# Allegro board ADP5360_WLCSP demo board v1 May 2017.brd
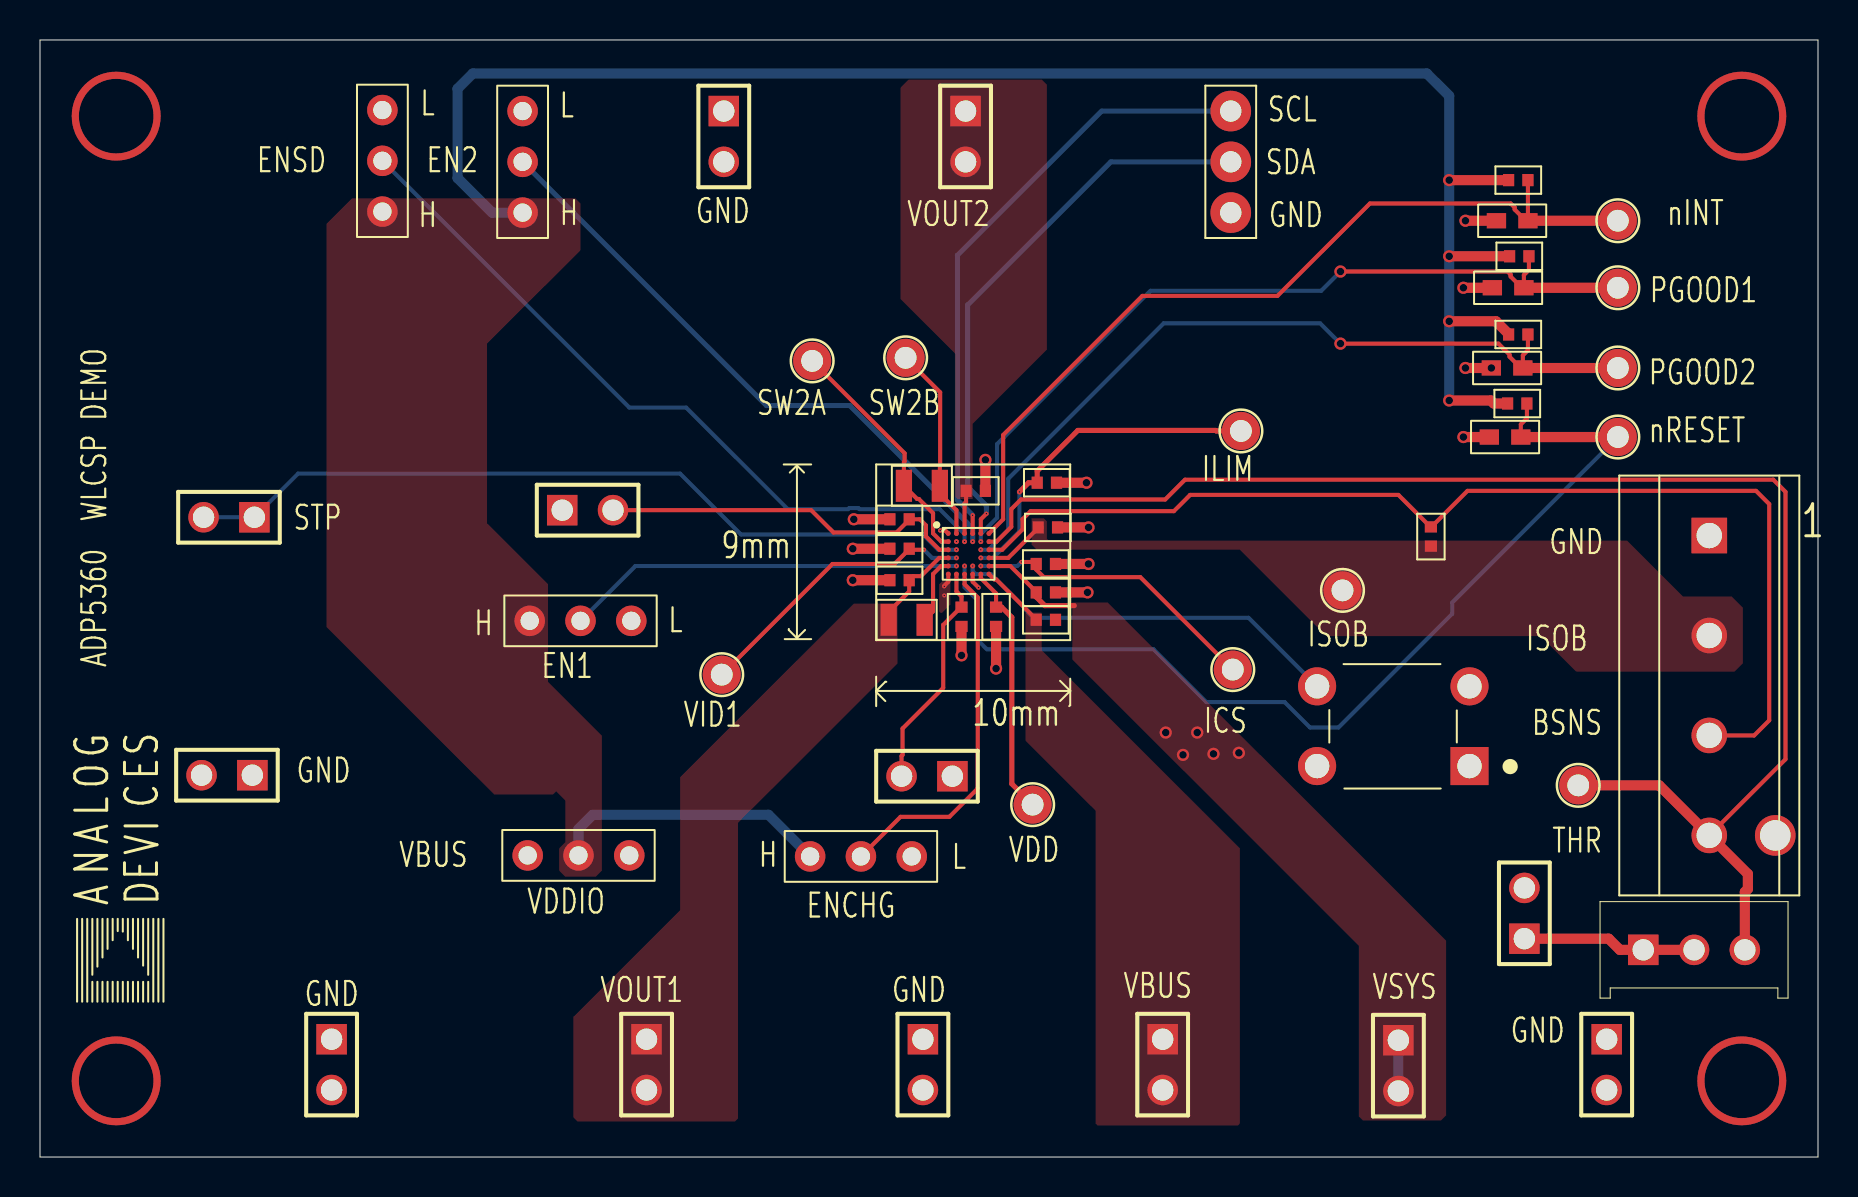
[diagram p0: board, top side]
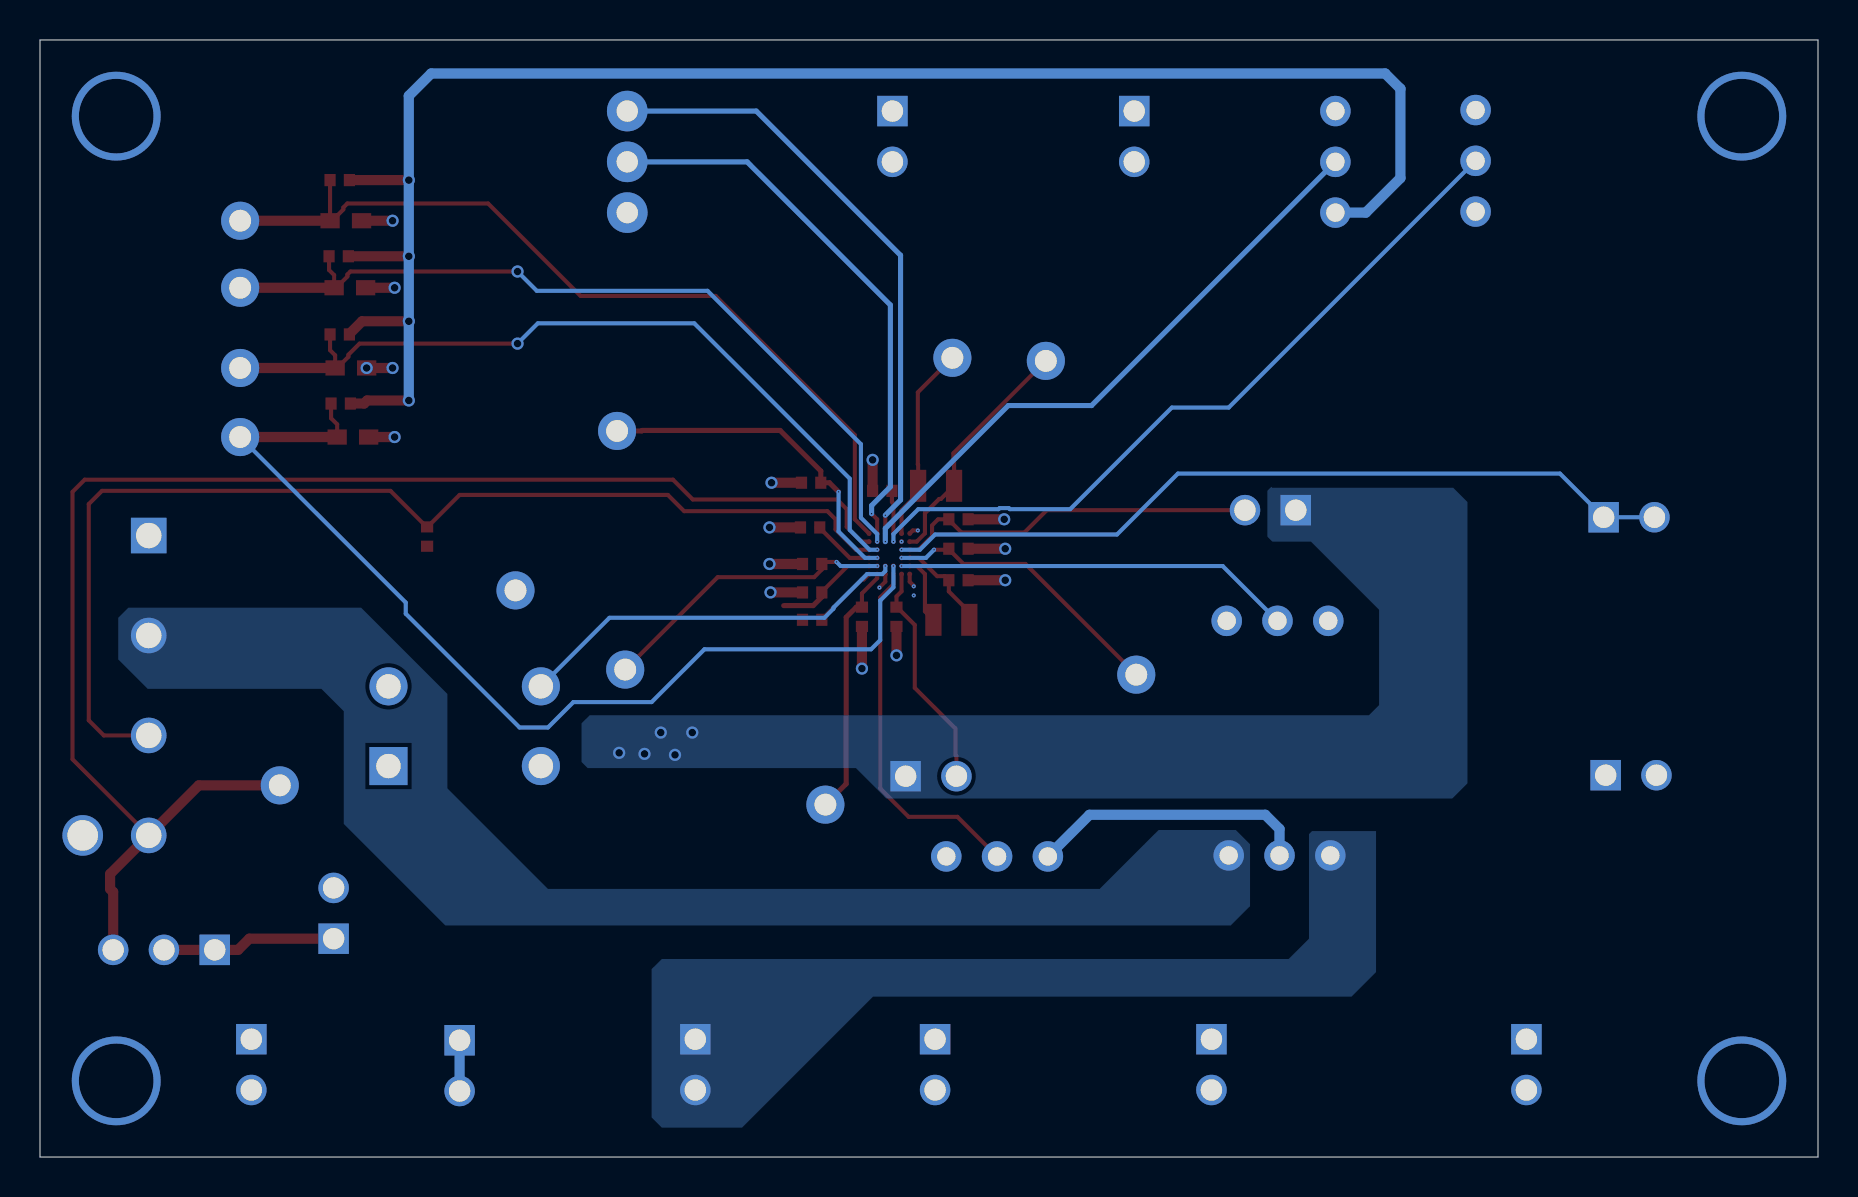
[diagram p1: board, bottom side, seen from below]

Outline 88.9 x 55.88 mm; copper layers: TOP, LAYER2, LAYER3, BOTTOM. Coordinates in mm from the lower left corner of the outline.

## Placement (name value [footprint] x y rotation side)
C1  2.2uF  [R0402]  50.29 26.87 0 top
C2  1uF  [R0402]  46.08 27.03 270 top
C3  1uF  [R0402]  47.8 27.03 270 top
C4  10uF  [R0402]  42.98 28.85 180 top
C5  1uF  [R0402]  50.29 28.24 0 top
C6  4.7uF  [R0402]  50.39 31.5 0 top
C7  1uF  [R0402]  42.98 31.9 180 top
C8  10uF  [R0402]  46.79 33.32 0 top
D1  LED  [CC0603]  73.61 46.84 180 top
D2  LED  [CC0603]  73.41 43.48 180 top
D3  LED  [CC0603]  73.36 39.47 180 top
D4  LED  [CC0603]  73.25 36.02 180 top
J1  VBUS  [HDR1X2]  56.13 5.89 90 top
J2  VSYS  [HDR1X2]  67.92 5.84 90 top
J3  VOUT1  [HDR1X2]  30.33 5.89 90 top
J4  4 HEADER  [CNTERM_4P-TYCO]  83.46 31.09 270 top
J5  STP  [HDR1X2]  10.72 32 0 top
J6  THR  [TESTPOINT75]  76.91 18.59 0 top
J7  VOUT2  [HDR1X2]  46.28 52.32 90 top
J8  I2C Connector  [JUMPER-3PIN]  59.54 47.24 0 top
J9  GND  [HDR1X2]  44.15 5.89 90 top
J10  GND  [HDR1X2]  78.33 5.89 90 top
J11  GND  [HDR1X2]  10.62 19.1 0 top
J12  GND  [HDR1X2]  14.58 5.89 90 top
J13  GND  [HDR1X2]  34.19 52.32 90 top
J18  1 Way Link  [HDR1X2]  74.22 10.92 270 top
JP1  2 Way Link  [JUMPER3]  24.49 26.82 0 top
JP2  2 Way Link  [JUMPER3]  38.51 15.04 0 top
JP3  2 Way Link  [JUMPER3]  24.13 47.24 90 top
JP4  2 Way Link  [JUMPER3]  17.12 47.29 90 top
JP5  2 Way Link  [JUMPER3]  24.38 15.09 0 top
L1  4.7uH  [INDUCTOR0806]  43.33 26.87 180 top
L2  4.7uH  [INDUCTOR0806]  44.09 33.58 0 top
NOREF  -  []  17.78 54.61 270 top
NOREF#2  -  []  -137.24 124.18 0 top
NOREF#3  -  []  0 0 90 top
NOREF#4  -  []  0 0 90 top
NOREF#5  -  []  0 50.8 0 top
R1  0R  [R0402]  69.55 31.04 270 top
R2  R_1  [R0402]  42.98 30.43 180 top
R3  R_1  [R0402]  50.34 33.73 180 top
R4  R_1  [R0402]  50.29 29.67 180 top
R5  5.1K  [R0402]  73.91 48.87 0 top
R6  5.1K  [R0402]  73.96 45.06 0 top
R7  5.1K  [R0402]  73.91 41.15 0 top
R8  5.1K  [R0402]  73.86 37.69 0 top
R9  THR  [SW_SPDT_MINI]  80.16 10.36 270 top
S1  Short  [HDR1X2]  45.62 19.05 0 top
S2  Short  [HDR1X2]  26.11 32.36 180 top
SW1  MR  [SWKT11]  71.48 19.56 180 top
T1  VDD  [TESTPOINT75]  49.63 17.63 0 top
T2  VID1  [TESTPOINT75]  34.09 24.13 0 top
T3  ISOB  [TESTPOINT75]  65.13 28.35 0 top
T4  ILIM  [TESTPOINT75]  60.05 36.32 0 top
T5  SW2A  [TESTPOINT75]  38.61 39.83 0 top
T6  ICS  [TESTPOINT75]  59.64 24.38 0 top
T7  SW2B  [TESTPOINT75]  43.28 39.98 0 top
T8  PGOOD1  [TESTPOINT75]  78.89 43.48 0 top
T9  nINT  [TESTPOINT75]  78.89 46.84 0 top
T10  RESET  [TESTPOINT75]  78.89 36.02 0 top
T11  PGOOD2  [TESTPOINT75]  78.89 39.47 0 top
U1  ADP5360  [ADP5360_WLCSP]  46.43 30.18 0 top

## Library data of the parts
C1-C8 = CAP/SM: Tolerance: TOL; User Part Number: UPN
D1-D4 = LED
J1-J3 J5 J7 J9-J13 = CON2
J4 = 4 HEADER: User Part Number: UPN; Tolerance: TOL
J6 T1-T11 = CON1_0
J8 = HEADER 3_0
J18 = 1_way_link
JP1-JP5 = 2_way_link: User Part Number: ***
L1 L2 = INDUCTOR/SM
R1-R8 = R_1: Tolerance: TOL; User Part Number: UPN
R9 = RESISTOR VAR
S1 S2 = Short Pad
SW1 = SW PUSHBUTTON_2: User Part Number: E004573; Tolerance: TOL
U1 = ADP5360_WLCSP

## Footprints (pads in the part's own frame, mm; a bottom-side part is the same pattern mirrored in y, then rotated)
ADP5360_WLCSP
  round 0.249 smd: A1(-1.021,1.021) A2(-0.61,1.016) A3(-0.203,1.016) A4(0.203,1.016) A5(0.61,1.016) A6(1.016,1.016) B1(-1.016,0.61) B2(-0.61,0.61) B3(-0.203,0.61) B4(0.203,0.61) B5(0.61,0.61) B6(1.016,0.61) C1(-1.016,0.203) C2(-0.61,0.203) C5(0.61,0.203) C6(1.016,0.203) D1(-1.016,-0.203) D2(-0.61,-0.203) D5(0.61,-0.203) D6(1.016,-0.203) E1(-1.016,-0.61) E2(-0.61,-0.61) E3(-0.203,-0.61) E4(0.203,-0.61) E5(0.61,-0.61) E6(1.016,-0.61) F1(-1.016,-1.016) F2(-0.61,-1.016) F3(-0.203,-1.016) F4(0.203,-1.016) F5(0.61,-1.016) F6(1.016,-1.016)
CC0603
  rect 0.965x0.762 smd: 1(-0.787,0) 2(0.787,0)
CNTERM_4P-TYCO
  round 2.032 hole 1.524: (15.001,3.299)
  rect 1.778x1.778 hole 1.27: 1(0,0)
  round 1.778 hole 1.27: 2(5.001,0) 3(10,0) 4(15.001,0)
HDR1X2
  rect 1.524x1.524 hole 1.067: 1(0,0)
  round 1.524 hole 1.067: 2(-2.54,0)
INDUCTOR0806
  rect 0.813x1.6 smd: 1(-0.899,0) 2(0.899,0)
JUMPER3
  round 1.524 hole 0.914: 1(0,0) 2(2.54,0) 3(5.08,0)
JUMPER-3PIN
  round 2.032 hole 1.067: 1(0,0) 2(0,2.54) 3(0,5.08)
R0402
  rect 0.559x0.61 smd: 1(-0.483,0) 2(0.483,0)
SW_SPDT_MINI
  rect 1.524x1.524 hole 1.067: 1(0,0)
  round 1.524 hole 1.067: 2(0,2.54) 3(0,5.08)
SWKT11
  rect 1.905x1.905 hole 1.219: 1(0,0)
  round 1.905 hole 1.219: 2(0,-3.988) 3(7.62,0) 4(7.62,-3.988)
TESTPOINT75
  round 1.905 hole 1.092: 1(0,0)

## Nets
GND: C1.2 C2.2 C3.2 C4.2 C5.2 C6.2 C7.2 C8.2 D1.2(CATHODE) D2.2(CATHODE) D3.2(CATHODE) D4.2(CATHODE) J4.1 J8.1 J9.1 J9.2 J10.1 J10.2 J11.1 J11.2 J12.1 J12.2 J13.1 J13.2 J18.2 JP1.3 JP2.3 JP3.3 JP4.3 R2.2 R3.1 R4.1 SW1.3 U1.A1(PGND2) U1.B2(AGND2) U1.F1(PGND1) U1.F4(AGND1)
VBUS: C1.1 J1.1 J1.2 JP5.1 U1.F6(VBUS)
VDD: C3.1 T1.1 U1.F5(VDD)
VDDIO: JP1.1 JP2.1 JP3.1 JP4.1 JP5.2(CENTER) R5.1 R6.1 R7.1 R8.1
VIN1: C2.1 S1.2 U1.F2(VIN1)
VIN2: C7.1 S2.2 U1.C1(VIN2)
BSNS: J4.3 R1.1 U1.C6(BSNS)
EN1: JP1.2(CENTER) U1.E2(EN1)
EN2: JP3.2(CENTER) U1.B4(EN2)
ENCHG: JP2.2(CENTER) U1.F3(ENCHG)
ENSD: JP4.2(CENTER) U1.B3(ENSD)
FB1: C4.1 J3.1 J3.2 L1.2 U1.D1(FB1)
ICS: R4.2 T6.1 U1.E5(ICS)
ILIM: R3.2 T4.1 U1.D5(ILIM)
ISOB: C6.1 J4.2 JP5.3 R1.2 T3.1 U1.D6(ISOB)
NINT: D1.1(ANODE) R5.2 T9.1 U1.A6(NINT)
NMR: SW1.4 U1.E4(NMR)
NRESET: D4.1(ANODE) R8.2 T10.1 U1.E3(NRESET)
PGOOD1: D2.1(ANODE) R6.2 T8.1 U1.B5(PGOOD1)
PGOOD2: D3.1(ANODE) R7.2 T11.1 U1.C5(PGOOD2)
SCL: J8.3 U1.A4(SCL)
SDA: J8.2 U1.A5(SDA)
STP: J5.1 J5.2 U1.C2(STP)
SW1: L1.1 U1.E1(SW1)
SW2A: L2.1 T5.1 U1.B1(SW2A)
SW2B: L2.2 T7.1 U1.A2(SW2B)
THR: J4.4 J6.1 R9.3(B) U1.B6(THR)
VID1: R2.1 T2.1 U1.D2(VID1)
VOUT2: C8.1 J7.1 J7.2 U1.A3(VOUT2)
VSYS: C5.1 J2.1 J2.2 S1.1 S2.1 U1.E6(VSYS)
N16513101: J18.1 R9.1(A) R9.2(WIPER)

Pads without a net: SW1 1 2

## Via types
v1: diameter 4.445, hole 3.734, TOP to BOTTOM, 4 vias
v2: diameter 0.203, hole 0.076, TOP to BOTTOM, 21 vias
v3: diameter 0.61, hole 0.381, TOP to BOTTOM, 26 vias

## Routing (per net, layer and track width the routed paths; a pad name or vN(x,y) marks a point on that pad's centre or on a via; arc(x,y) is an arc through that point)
GND: length 24.5
  TOP w0.203: U1.F1 45.42,28.78 45.21,28.58 v2(45.21,28.55) ; v2(45.01,31.34) 45.26,31.34 U1.A1 ; U1.F4 46.63,28.78 v2(46.93,28.49)
  TOP w0.508: R2.2 v3(40.64,30.43) ; D1.2 v3(71.27,46.84) ; D4.2 v3(71.17,36.02) ; C2.2 v3(46.08,25.1) ; C3.2 v3(47.8,24.43) ; C7.2 v3(40.69,31.9) ; R3.1 v3(52.32,33.73) ; C8.2 v3(47.27,34.87) ; C6.2 v3(52.43,31.5) ; C5.2 v3(52.37,28.24) ; C4.2 v3(40.64,28.85) ; R4.1 v3(52.43,29.67) ; D2.2 v3(71.17,43.48) ; v3(72.57,39.47) v3(71.27,39.47)
  vias: v1(3.81,52.07) v1(3.81,3.81) v1(85.09,52.07) v2(45.21,28.09) v2(45.82,30.78)
VBUS: length 3.5
  TOP w0.203: 49.91,26.77 49.91,26.8 47.82,28.89 47.71,28.89 U1.F6
VDD: length 12.8
  TOP w0.203: C3.1 47.8,28.19 47.04,28.96 U1.F5
  TOP w0.254: C3.1 48.08,27.51 48.59,27 48.59,18.67 T1.1
VDDIO: length 100.3
  TOP w0.508: v3(70.46,37.85) 72.54,37.85 72.69,37.69 R8.1 ; R5.1 v3(70.46,48.87) ; R6.1 v3(70.46,45.06) ; R7.1 73.43,41.17 72.8,41.81 v3(70.46,41.81)
  BOTTOM w0.508: v3(70.46,37.85) v3(70.46,41.81) v3(70.46,45.06) v3(70.46,48.87) 70.46,53.09 69.34,54.2 21.64,54.2 20.88,53.44 20.88,48.97 22.61,47.24 JP3.1 ; JP5.2 26.92,16.41 27.64,17.12 36.42,17.12 JP2.1
VIN1: length 11.5
  TOP w0.203: U1.F2 45.82,28.3 46.08,28.04 C2.1 46.05,27.51 45.16,26.62 45.16,23.47 43.13,21.44 43.13,20.12 43.08,20.07 S1.2
VIN2: length 18.5
  TOP w0.203: S2.2 38.56,32.36 39.67,31.24 42.82,31.24 43.46,31.88 C7.1 43.99,31.9 44.3,31.6 44.3,31.05 44.97,30.38 U1.C1
BSNS: length 56.3
  TOP w0.203: U1.C6 48.11,30.38 49.12,31.39 49.12,31.9 49.53,32.31 56.69,32.31 57.51,33.12 67.92,33.12 69.52,31.52 R1.1 69.57,31.52 71.37,33.32 85.8,33.32 86.46,32.66 86.46,21.84 85.71,21.09 J4.3
EN1: length 19.9
  BOTTOM w0.203: JP1.2 29.77,29.57 v2(45.82,29.57)
EN2: length 30.8
  BOTTOM w0.254: v2(46.63,30.78) 46.63,31.45 40.49,37.59 36.32,37.59 JP3.2
ENCHG: length 18.2
  TOP w0.203: U1.F3 46.23,28.65 46.89,27.99 46.89,18.44 45.47,17.02 43.03,17.02 JP2.2
ENSD: length 37.3
  BOTTOM w0.203: v2(46.23,30.78) 46.23,31.17 44.98,32.41 40.97,32.41 40.92,32.46 40.46,32.46 40.41,32.41 37.39,32.41 32.31,37.49 29.46,37.49 JP4.2
FB1: length 4.8
  TOP w0.203: U1.D1 44.96,29.97 44.04,29.06 43.66,29.06 C4.1 43.46,28.29 42.43,27.27 L1.2
ICS: length 15.1
  TOP w0.203: T6.1 55.02,29.01 50.19,29.01 49.81,29.39 R4.2 49.71,29.77 v2(49.07,29.77)
  BOTTOM w0.203: v2(49.07,29.77) 48.87,29.57 v2(47.04,29.57)
ILIM: length 17.2
  TOP w0.254: v2(48.97,33.27) 49.43,33.73 R3.2 49.86,34.32 51.89,36.35 58.79,36.35 58.81,36.32 T4.1
  BOTTOM w0.203: v2(48.97,33.27) 48.97,31.29 47.65,29.97 v2(47.04,29.97)
ISOB: length 3.1
  TOP w0.203: 49.91,31.47 48.41,29.97 U1.D6
  TOP w0.508: C6.1 49.91,31.47
Net_9:
  vias: v1(85.09,3.81)
NINT: length 43.2
  TOP w0.203: U1.A6 48.16,31.9 48.16,36.12 55.12,43.08 61.87,43.08 66.5,47.7 73.53,47.7 73.73,47.5 73.73,47.4 74.3,46.84 D1.1 R5.2
  TOP w0.508: D1.1 T9.1
NMR: length 19.9
  BOTTOM w0.203: v2(46.63,29.57) 46.63,29.31 46.79,29.16 47.55,29.16 49.23,27.48 49.23,27.43 49.68,26.97 60.43,26.97 SW1.4
NRESET: length 50.8
  TOP w0.203: R8.2 74.35,36.96 74.04,36.65 D4.1
  TOP w0.508: D4.1 T10.1
  BOTTOM w0.203: T10.1 70.61,27.74 70.61,27.18 64.92,21.49 63.5,21.49 62.23,22.76 58.32,22.76 55.68,25.4 47.35,25.4 46.89,25.86 46.89,27.84 46.23,28.5 v2(46.23,29.57)
PGOOD1: length 55.9
  TOP w0.203: v3(65.02,44.3) 73.38,44.3 73.53,44.15 73.53,44.05 74.09,43.48 D2.1 74.19,44.12 74.45,44.37 R6.2
  TOP w0.508: D2.1 T8.1
  LAYER3 w0.203: 78.64,43.38 77.72,44.3 v3(65.02,44.3)
  BOTTOM w0.203: v2(47.04,30.78) 47.04,31.17 47.85,31.98 47.85,35.66 55.52,43.33 64.06,43.33 v3(65.02,44.3)
PGOOD2: length 40.8
  TOP w0.203: v3(65.02,40.69) 72.92,40.69 73.48,40.13 73.48,40.03 74.04,39.47 D3.1 74.14,40.11 74.4,40.36 R7.2
  TOP w0.508: D3.1 T11.1
  BOTTOM w0.203: v2(47.04,30.38) 47.42,30.38 48.41,31.37 48.41,33.93 56.18,41.71 64.01,41.71 v3(65.02,40.69)
SCL: length 30.9
  TOP w0.203: U1.A4 v2(46.63,32.11)
  BOTTOM w0.254: v2(46.63,32.11) 45.87,32.87 45.87,45.11 53.09,52.32 J8.3
SDA: length 28.1
  TOP w0.203: v2(47.32,32.18) 47.04,31.9 U1.A5
  BOTTOM w0.254: v2(47.32,32.18) 47.32,32.59 46.38,33.53 46.38,42.62 53.54,49.78 J8.2
STP: length 40.1
  BOTTOM w0.203: J5.2 J5.1 12.9,34.19 32,34.19 35.05,31.14 44.15,31.14 44.91,30.38 v2(45.82,30.38)
SW1: length 3.4
  TOP w0.203: L1.1 44.65,27.29 44.65,29.16 45.05,29.57 U1.E1
SW2A: length 12.1
  TOP w0.203: T5.1 43.23,35.2 43.23,34.8 43.2,34.76 L2.1 43.86,32.92 43.94,32.92 44.65,32.21 44.65,31.2 45.06,30.78 U1.B1
SW2B: length 9.9
  TOP w0.203: U1.A2 45.82,32.36 44.99,33.19 L2.2 44.99,34.63 45.01,34.65 45.01,38.25 T7.1
THR: length 74.8
  TOP w0.203: U1.B6 47.83,30.78 48.56,31.52 48.56,32.41 49.05,32.89 56.26,32.89 57.25,33.88 86.66,33.88 87.27,33.27 87.27,19.9 J4.4
  TOP w0.508: R9.3 85.24,13.26 85.39,13.41 85.39,14.16 J4.4 80.96,18.59 J6.1
VID1: length 14.5
  TOP w0.203: v2(44.2,30.38) 43.51,30.38 R2.1 43.46,30.4 42.72,29.67 39.62,29.67 T2.1
  BOTTOM w0.203: v2(44.2,30.38) 44.6,29.97 v2(45.82,29.97)
VOUT2: length 2.2
  TOP w0.203: C8.1 46.3,32.77 46.23,32.69 U1.A3
VSYS: length 7.8
  TOP w0.203: C5.1 49.81,28.27 48.51,29.57 U1.E6
  TOP w0.254: C5.1 49.81,28.02 50.24,27.58 51.71,27.58
  BOTTOM w0.508: J2.1 J2.2
  vias: v3(56.29,21.23) v3(57.15,20.12) v3(57.86,21.23) v3(58.67,20.17) v3(59.94,20.22)
N16513101: length 8.7
  TOP w0.508: J18.1 78.44,10.92 78.99,10.36 R9.1 R9.2

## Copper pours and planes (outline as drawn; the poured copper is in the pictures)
GND on LAYER2: 1.07,55.12 1.07,0.61 87.63,0.61 87.63,55.12
GND on LAYER2, LAYER3: 9.4,1.02 9.4,7.49 1.52,7.49 1.52,48.39 9.4,48.39 9.4,54.74 81.15,54.74 81.15,48.26 87.5,48.26 87.5,6.86 80.9,6.86 80.9,1.02
VBUS on TOP: 59.99,1.68 59.99,15.44 50.09,25.35 50.09,27.23 49.28,27.23 49.28,20.83 52.78,17.32 52.78,1.68 52.88,1.57 59.89,1.57
VBUS on BOTTOM: 22.1,16.31 25.3,16.31 25.45,16.15 25.45,10.92 26.47,9.91 57.81,9.91 58.32,9.4 58.32,1.98 57.81,1.47 53.8,1.47 47.24,8.03 23.32,8.03 22.1,9.25
VDDIO on TOP: 26.77,47.96 15.6,47.96 14.33,46.69 14.33,26.52 22.71,18.14 25.65,18.14 25.81,18.29 26.26,17.83 26.26,15.75 25.96,15.44 25.96,14.33 26.26,14.02 27.79,14.02 28.09,14.33 28.09,21.08 25.4,23.77 25.4,28.65 22.35,31.7 22.35,40.69 27.03,45.36 27.03,47.7
FB1 on TOP: 34.9,1.93 34.9,16.71 42.88,24.69 42.88,27.69 40.69,27.69 32,19 32,12.34 26.67,7.01 26.67,1.98 26.87,1.78 34.75,1.78
ISOB on TOP: 49.58,31.95 50.19,31.95 50.34,31.8 50.34,30.94 50.44,30.84 79.35,30.84 82.14,28.04 84.58,28.04 85.14,27.48 85.14,24.69 84.73,24.28 76.81,24.28 75.03,26.06 64.31,26.06 59.99,30.38 49.83,30.38 49.58,30.63
ISOB on BOTTOM: 29.11,16.36 32.97,16.36 35.92,13.41 63.5,13.41 68.53,18.44 68.53,23.16 72.85,27.48 84.48,27.48 84.99,26.97 84.99,24.89 83.52,23.42 74.83,23.42 73.71,22.3 73.71,16.66 68.63,11.58 29.36,11.58 28.4,12.55 28.4,15.65
VOUT2 on TOP: 50.34,53.64 50.34,40.39 46.63,36.68 46.63,32.92 45.87,32.92 45.77,33.02 45.77,40.18 43.03,42.93 43.03,53.49 43.43,53.9 50.09,53.9
VSYS on TOP: 51.61,27.74 53.39,27.74 70.31,10.82 70.31,2.08 70.05,1.83 66.14,1.83 65.94,2.03 65.94,10.57 51.61,24.89
VSYS on BOTTOM: 27.28,33.48 18.24,33.48 17.53,32.77 17.53,18.69 18.29,17.93 46.58,17.93 48.11,19.46 61.52,19.46 61.82,19.76 61.82,21.69 61.42,22.1 22.45,22.1 21.95,22.61 21.95,27.38 25.35,30.78 27.28,30.78 27.53,31.04 27.53,33.32 27.33,33.53

Small or netless copper shapes (teardrops, artwork), in the pictures only: 1 on TOP

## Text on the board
Ref Des/Silkscreen Top: ENSD | STP | GND | VBUS | H | L | EN2 | VDDIO | EN1 | VOUT1 | VID1 | SW2A | ENCHG | SW2B | VOUT2 | VDD | ILIM | ICS | SDA | SCL | ISOB | VSYS | BSNS | THR | PGOOD2 | nRESET | PGOOD1 | nINT | ADP5360  WLCSP DEMO | 9mm | 10mm | G | O | A | N | S | E | C | I | V | D
User.6: 3 | CORRECT DISCONNECTED PINS C72 | 9/04/08 | JW
